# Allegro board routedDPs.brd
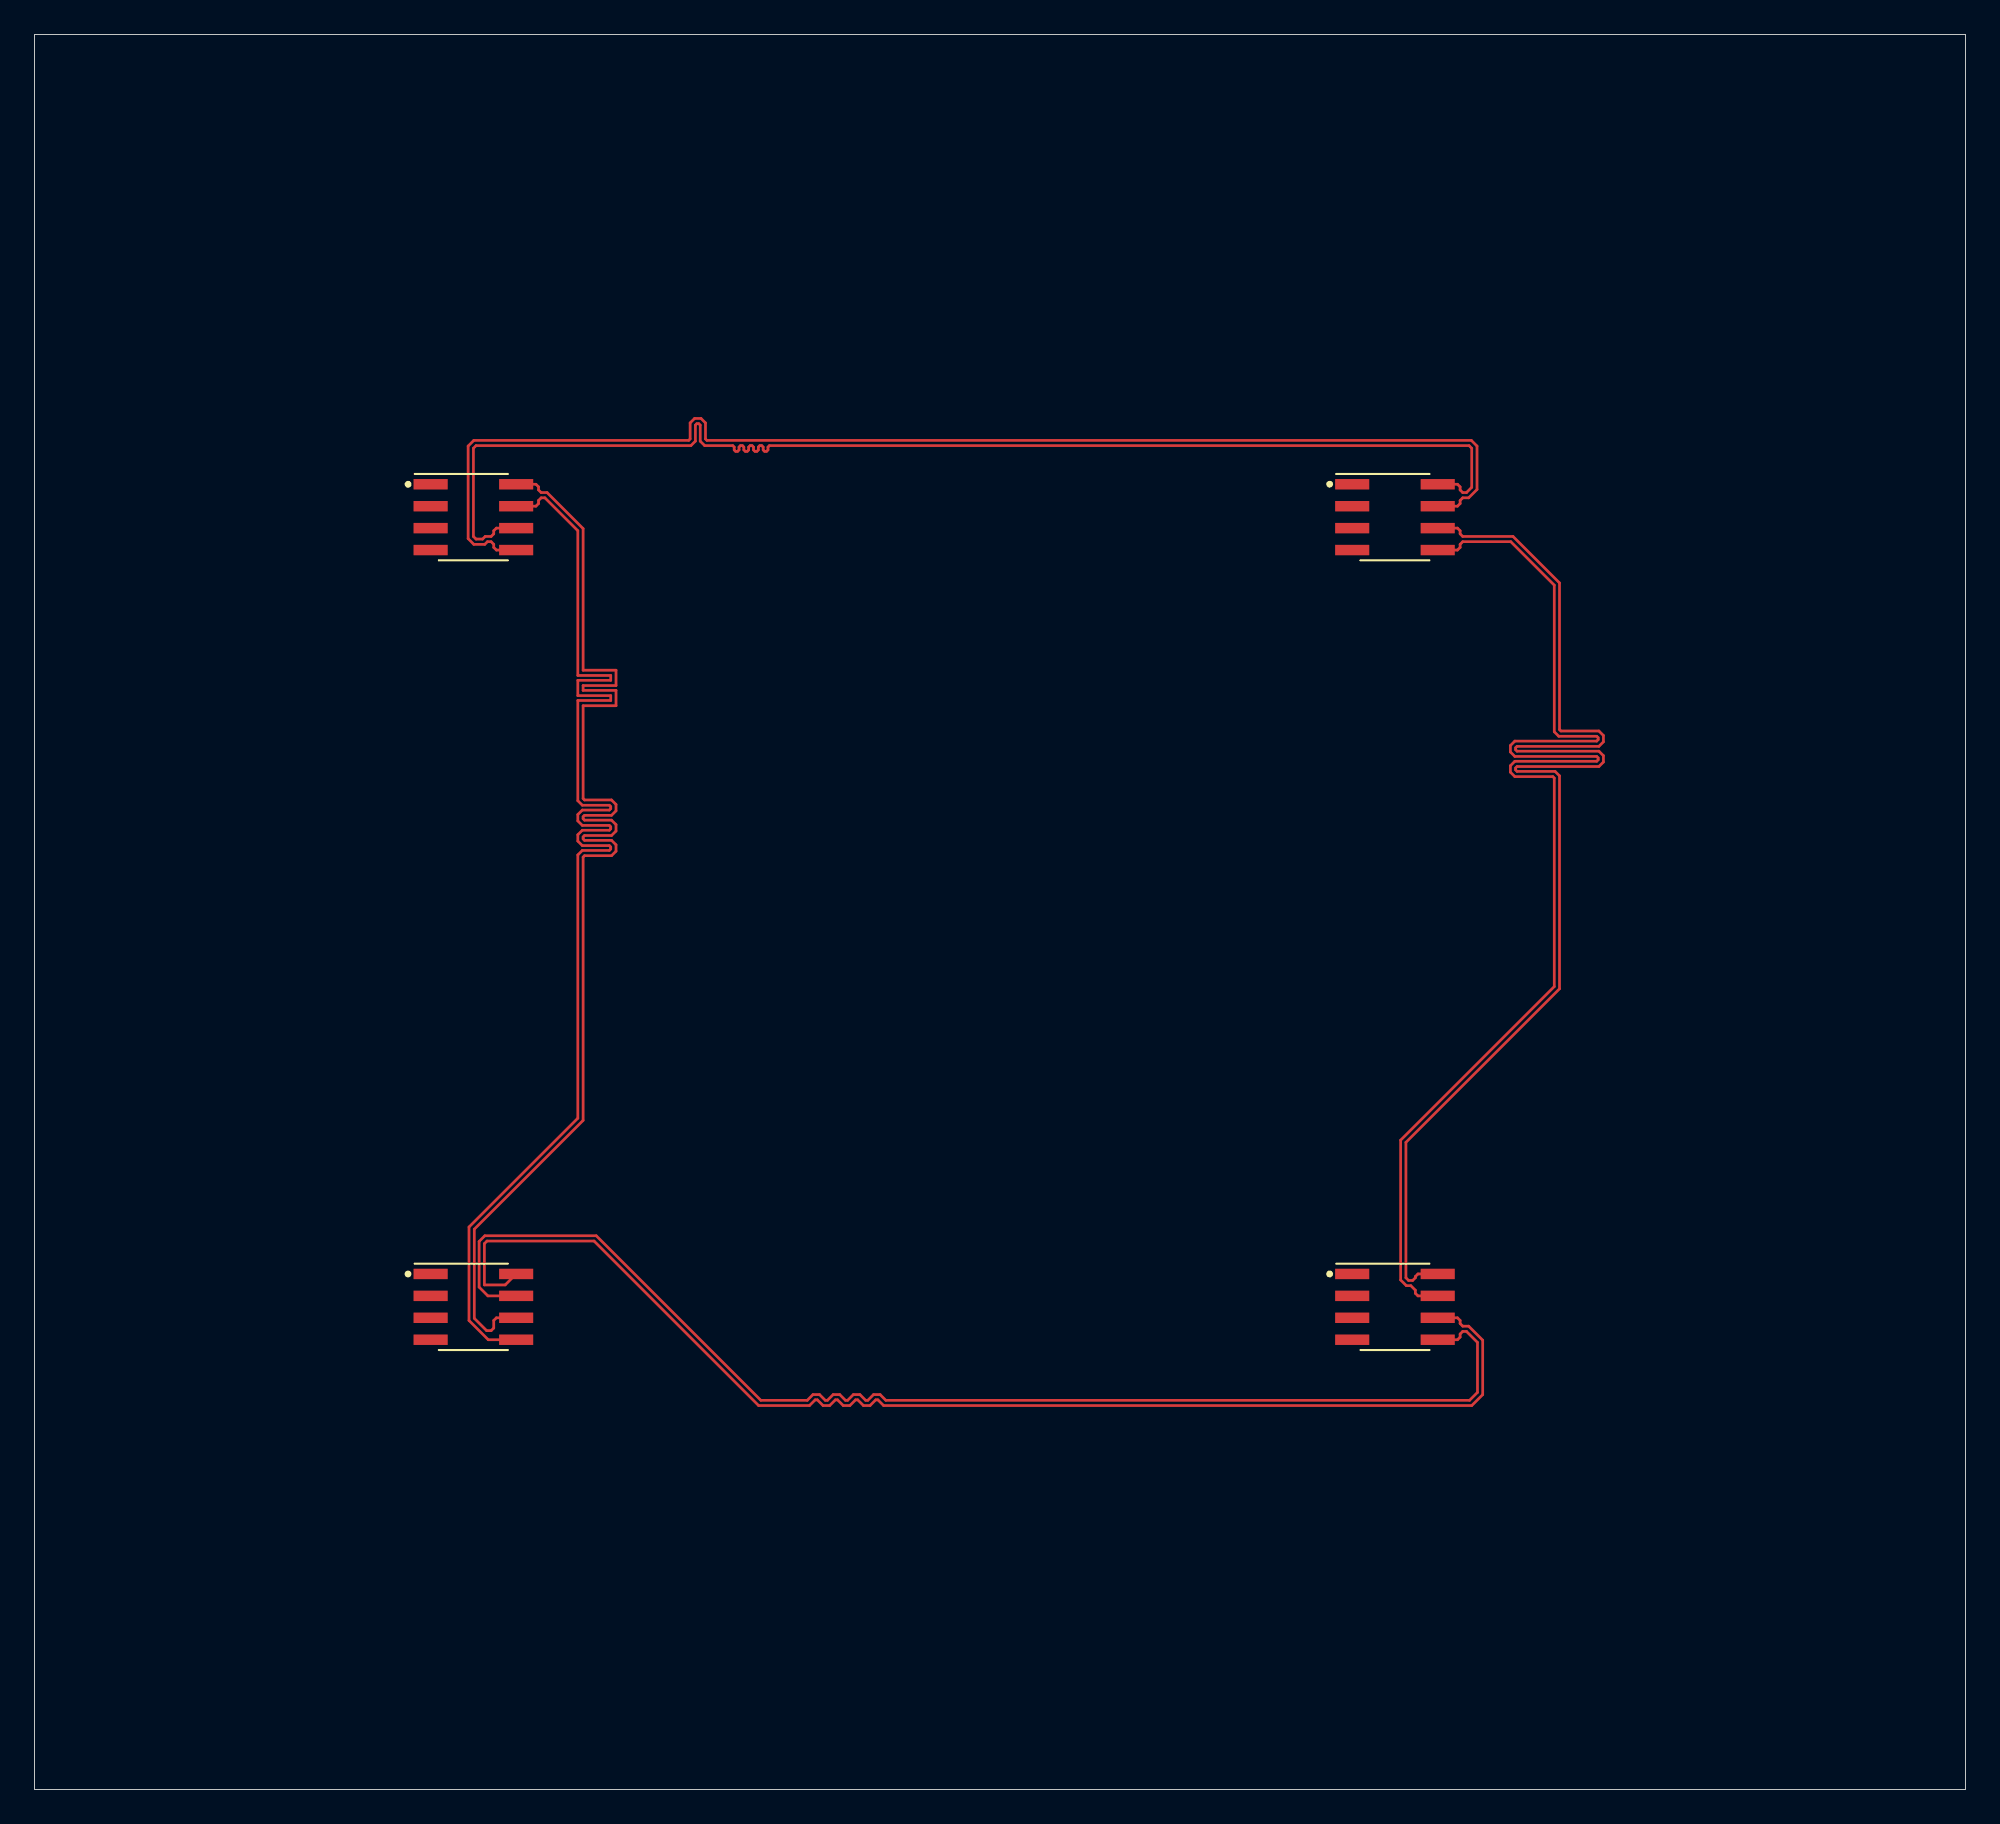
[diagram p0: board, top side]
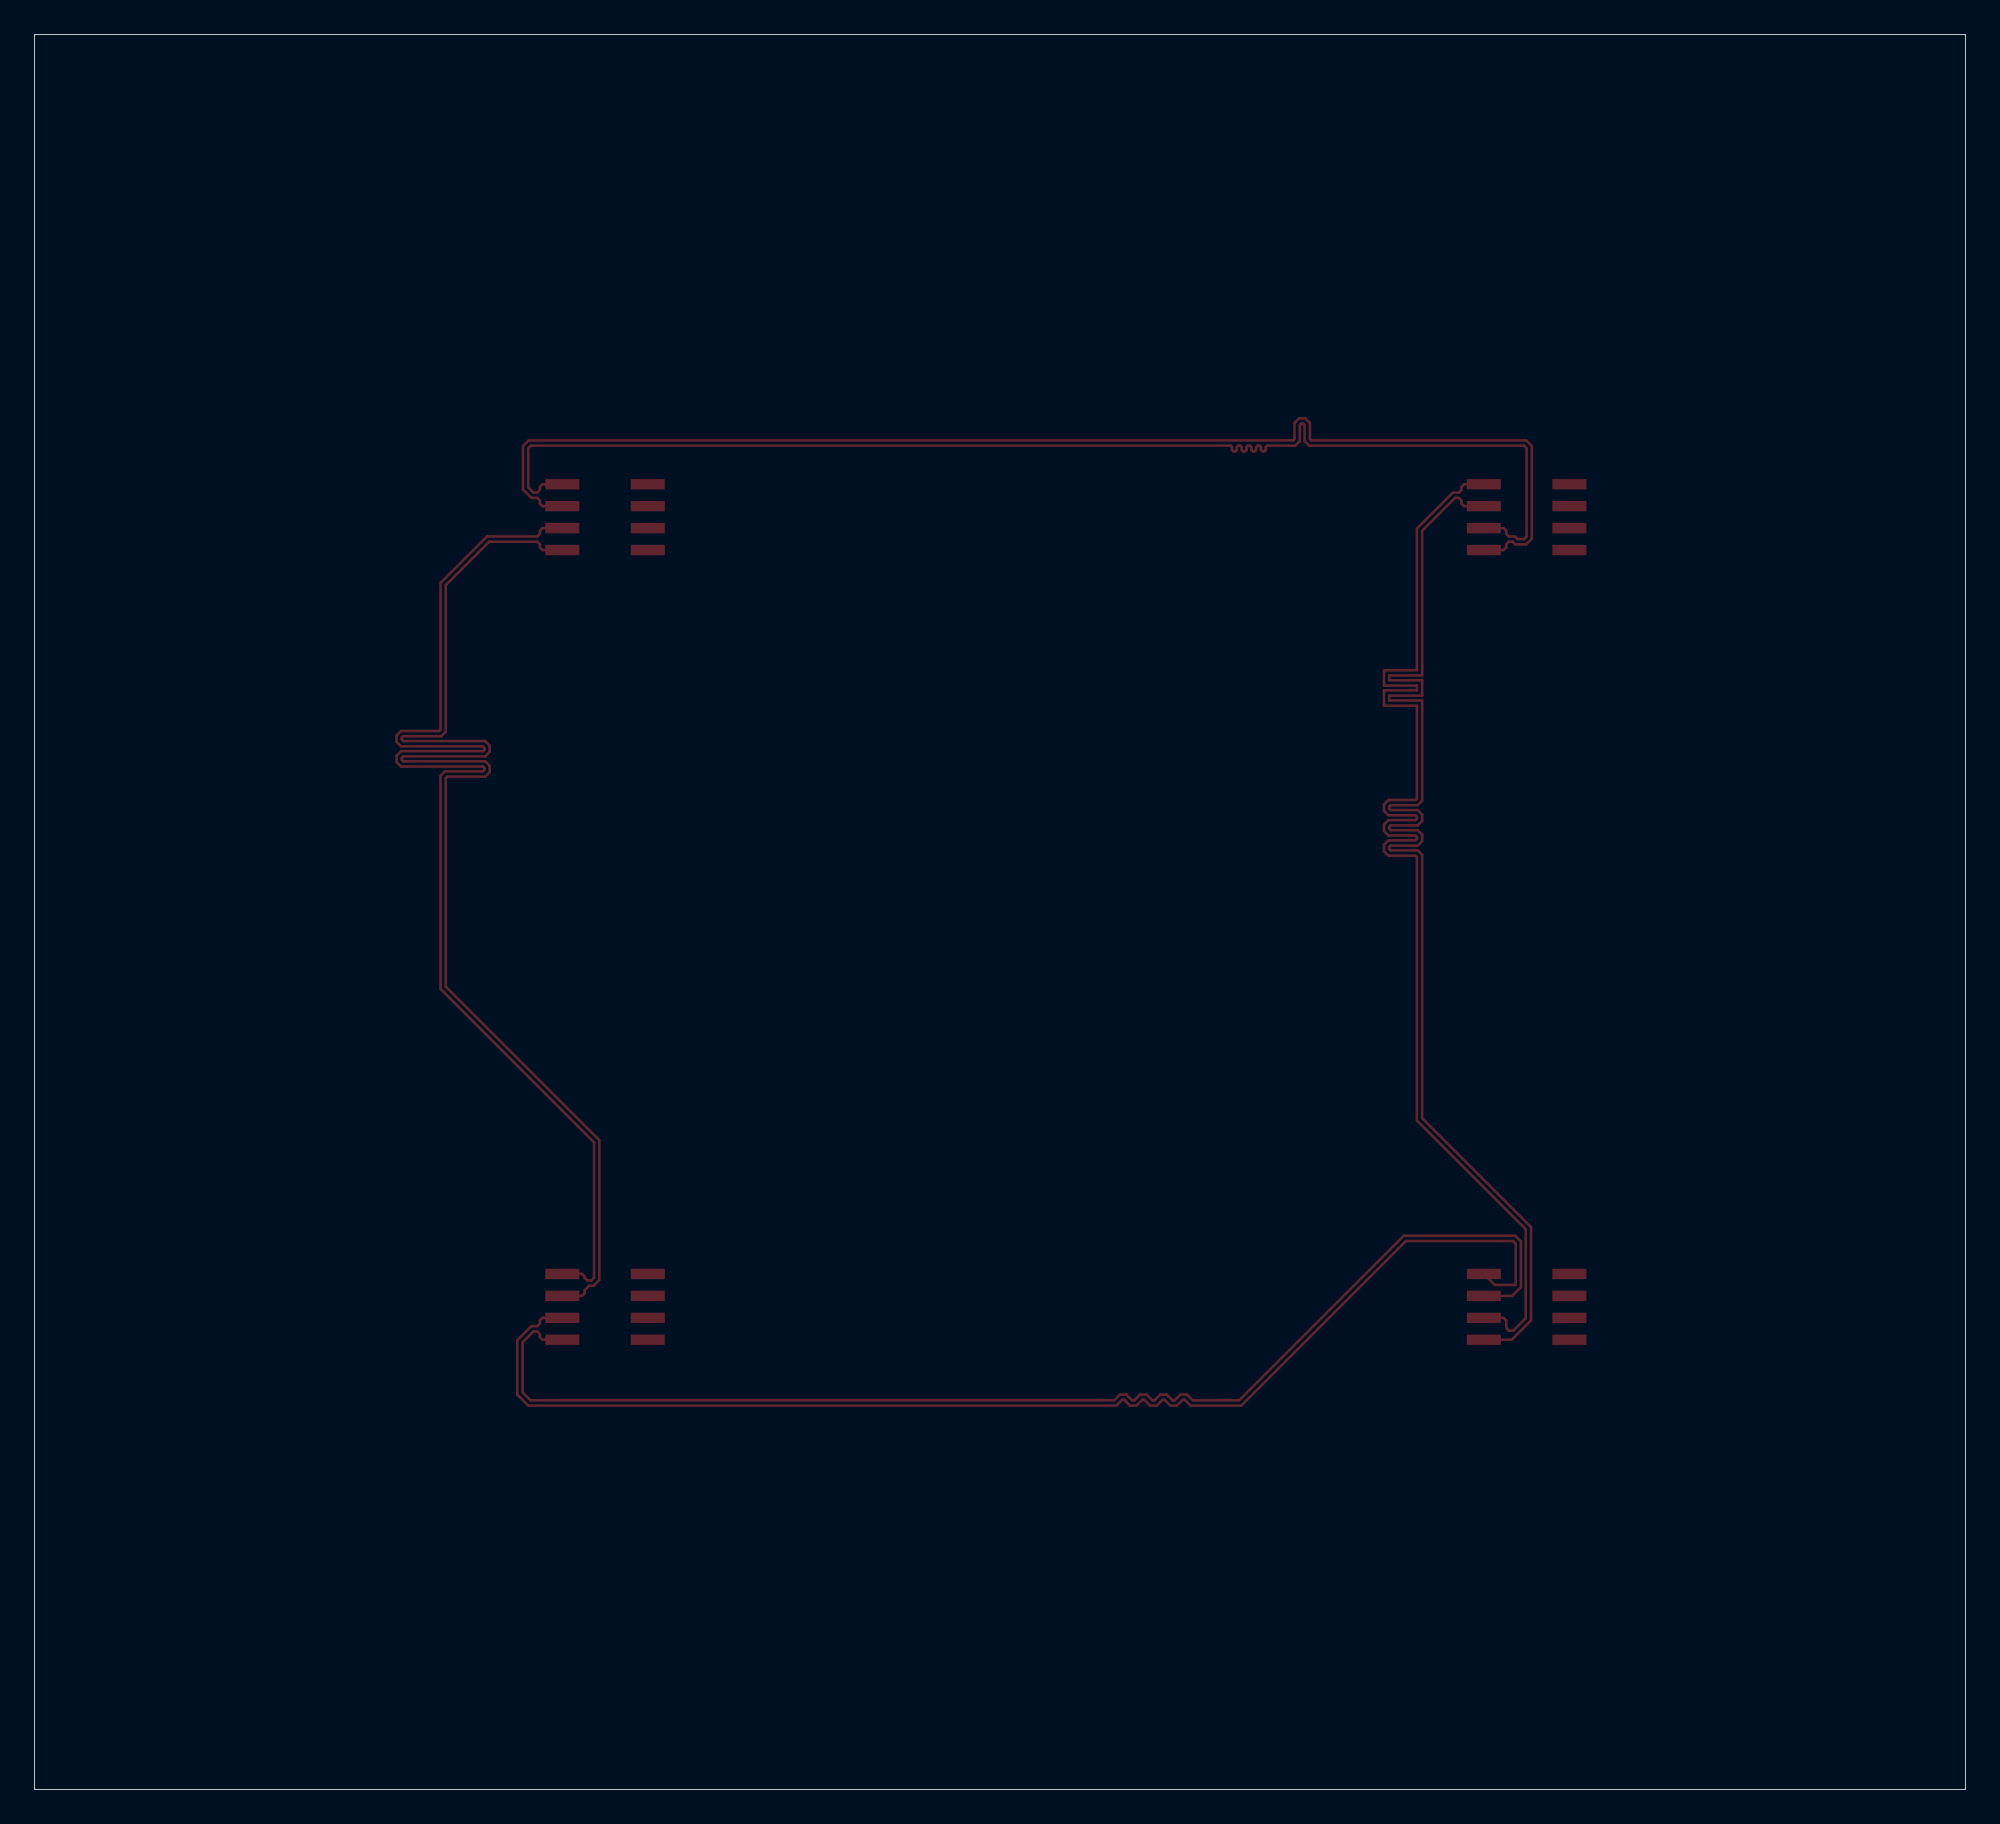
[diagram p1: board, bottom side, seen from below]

Outline 111.76 x 101.6 mm; copper layers: TOP, GND, VCC, BOTTOM. Coordinates in mm from the lower left corner of the outline.
Outline path: 0,101.6 0,0 111.76,0 111.76,101.6 0,101.6

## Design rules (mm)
net group D3: nets D3N D3P
net group D4: nets D4N D4P

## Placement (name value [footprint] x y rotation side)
U1  DS89C21  [SOIC127P600X175-8L87N]  25.4 73.66 270 top
U2  DS89C21  [SOIC127P600X175-8L87N]  78.74 73.66 270 top
U3  DS89C21  [SOIC127P600X175-8L87N]  78.74 27.94 270 top
U4  DS89C21  [SOIC127P600X175-8L87N]  25.4 27.94 270 top

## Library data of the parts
U1-U4 = DS89C21

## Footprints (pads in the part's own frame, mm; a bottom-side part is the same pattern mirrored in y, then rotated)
SOIC127P600X175-8L87N
  rect 0.6x1.97 smd: 1(-1.905,-2.475) 2(-0.635,-2.475) 3(0.635,-2.475) 4(1.905,-2.475) 5(1.905,2.475) 6(0.635,2.475) 7(-0.635,2.475) 8(-1.905,2.475)

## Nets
GND: U1.4(GND) U2.4(GND) U3.4(GND) U4.4(GND)
VCC: U1.1(VCC) U2.1(VCC) U3.1(VCC) U4.1(VCC)
D1N: U1.5(D_N) U2.7(R_N)
D1P: U1.6(D_P) U2.8(R_P)
D2N: U2.5(D_N) U3.7(R_N)
D2P: U2.6(D_P) U3.8(R_P)
D3N: U3.5(D_N) U4.7(R_N)
D3P: U3.6(D_P) U4.8(R_P)
D4N: U1.7(R_N) U4.5(D_N)
D4P: U1.8(R_P) U4.6(D_P)
X1: U1.2(RO) U2.3(DI)
X2: U2.2(RO) U3.3(DI)
X3: U3.2(RO) U4.3(DI)
X4: U1.3(DI) U4.2(RO)

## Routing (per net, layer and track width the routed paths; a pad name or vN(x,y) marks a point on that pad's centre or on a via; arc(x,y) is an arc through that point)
D1N: length 74.7
  TOP w0.152: U2.7 82.36,74.3 82.51,74.45 82.51,74.63 82.66,74.78 83.01,74.78 83.49,75.26 83.49,77.77 83.16,78.11 38.92,78.11 38.83,78.19 38.83,79.11 38.57,79.38 38.2,79.38 37.94,79.11 37.94,78.19 37.86,78.11 25.43,78.11 25.1,77.77 25.1,72.42 25.43,72.09 26.06,72.09 26.21,72.24 26.43,72.24 26.58,72.09 26.58,71.91 26.73,71.75 U1.5
D1P: length 74.6
  TOP w0.152: U1.6 26.73,73.02 26.58,72.87 26.58,72.69 26.43,72.54 26.08,72.54 25.93,72.39 25.55,72.39 25.4,72.54 25.4,77.65 25.55,77.8 37.99,77.8 38.25,78.06 38.25,78.99 38.33,79.07 38.45,79.07 38.53,78.99 38.53,78.06 38.79,77.8 40.41,77.8 40.5,77.72 40.5,77.55 40.58,77.47 40.69,77.47 40.77,77.55 40.77,77.72 40.86,77.8 40.97,77.8 41.05,77.72 41.05,77.55 41.14,77.47 41.25,77.47 41.33,77.55 41.33,77.72 41.42,77.8 41.53,77.8 41.61,77.72 41.61,77.55 41.69,77.47 41.81,77.47 41.89,77.55 41.89,77.72 41.97,77.8 42.09,77.8 42.17,77.72 42.17,77.55 42.25,77.47 42.37,77.47 42.45,77.55 42.45,77.72 42.53,77.8 83.03,77.8 83.19,77.65 83.19,75.39 82.88,75.08 82.66,75.08 82.51,75.23 82.51,75.41 82.36,75.56 U2.8
D2N: length 73.9
  TOP w0.152: U3.7 80.07,28.58 79.92,28.73 79.92,28.91 79.66,29.17 79.4,29.17 79.07,29.5 79.07,37.59 87.96,46.48 87.96,58.56 87.88,58.64 85.68,58.64 85.42,58.9 85.42,59.27 85.68,59.53 90.42,59.53 90.5,59.61 90.5,59.72 90.42,59.81 85.68,59.81 85.42,60.07 85.42,60.43 85.68,60.69 90.42,60.69 90.5,60.78 90.5,60.89 90.42,60.97 88.22,60.97 87.96,61.23 87.96,69.72 85.45,72.24 82.66,72.24 82.51,72.09 82.51,71.91 82.36,71.75 U2.5
D2P: length 73.8
  TOP w0.152: U2.6 82.36,73.02 82.51,72.87 82.51,72.69 82.66,72.54 85.57,72.54 88.27,69.85 88.27,61.36 88.35,61.28 90.54,61.28 90.8,61.02 90.8,60.65 90.54,60.39 85.81,60.39 85.72,60.31 85.72,60.19 85.81,60.11 90.54,60.11 90.8,59.85 90.8,59.48 90.54,59.22 85.81,59.22 85.72,59.14 85.72,59.02 85.81,58.94 88,58.94 88.27,58.68 88.27,46.35 79.38,37.46 79.38,29.62 79.53,29.47 79.77,29.47 79.92,29.62 79.92,29.69 80.07,29.84 U3.8
D3N: length 73.9
  TOP w0.152: U3.5 82.36,26.03 82.51,26.19 82.51,26.37 82.66,26.52 82.88,26.52 83.52,25.88 83.52,22.99 83.06,22.53 49.27,22.53 48.94,22.86 48.56,22.86 48.23,22.53 48.1,22.53 47.77,22.86 47.39,22.86 47.06,22.53 46.93,22.53 46.6,22.86 46.22,22.86 45.89,22.53 45.77,22.53 45.44,22.86 45.06,22.86 44.72,22.53 42.04,22.53 32.51,32.05 26.06,32.05 25.73,31.72 25.73,29.08 26.24,28.58 U4.7
D3P: length 74
  TOP w0.152: U4.8 27.24,29.21 26.03,29.21 26.03,31.6 26.19,31.75 32.38,31.75 41.91,22.23 44.85,22.23 45.18,22.56 45.31,22.56 45.64,22.23 46.02,22.23 46.35,22.56 46.48,22.56 46.81,22.23 47.19,22.23 47.52,22.56 47.65,22.56 47.98,22.23 48.36,22.23 48.69,22.56 48.81,22.56 49.14,22.23 83.19,22.23 83.82,22.86 83.82,26.01 83.01,26.82 82.66,26.82 82.51,26.97 82.51,27.15 82.36,27.3 U3.6
D4N: length 74
  TOP w0.152: U1.7 29.02,74.3 29.17,74.45 29.17,74.63 29.32,74.78 29.54,74.78 31.45,72.87 31.45,64.49 33.35,64.49 33.35,64.21 31.45,64.21 31.45,63.33 33.35,63.33 33.35,63.05 31.45,63.05 31.45,57.24 31.71,56.98 33.27,56.98 33.35,56.9 33.35,56.78 33.27,56.7 31.71,56.7 31.45,56.44 31.45,56.07 31.71,55.81 33.27,55.81 33.35,55.73 33.35,55.62 33.27,55.53 31.71,55.53 31.45,55.27 31.45,54.9 31.71,54.64 33.27,54.64 33.35,54.56 33.35,54.45 33.27,54.37 31.71,54.37 31.45,54.11 31.45,38.86 25.15,32.56 25.15,27.15 26.26,26.03 U4.5
D4P: length 74.5
  TOP w0.152: U4.6 26.73,27.3 26.58,27.15 26.58,26.71 26.43,26.56 26.17,26.56 25.45,27.28 25.45,32.44 31.75,38.73 31.75,53.98 31.83,54.06 33.39,54.06 33.66,54.32 33.66,54.69 33.39,54.95 31.83,54.95 31.75,55.03 31.75,55.15 31.83,55.23 33.39,55.23 33.66,55.49 33.66,55.86 33.39,56.12 31.83,56.12 31.75,56.2 31.75,56.32 31.83,56.4 33.39,56.4 33.66,56.66 33.66,57.03 33.39,57.29 31.83,57.29 31.75,57.37 31.75,62.74 33.66,62.74 33.66,63.63 31.75,63.63 31.75,63.91 33.66,63.91 33.66,64.8 31.75,64.8 31.75,73 29.67,75.08 29.32,75.08 29.17,75.23 29.17,75.41 29.02,75.56 U1.8

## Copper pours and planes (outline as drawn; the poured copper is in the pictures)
GND on GND: 0.51,101.09 111.25,101.09 111.25,0.51 0.51,0.51
Net_1 on VCC: 0.51,101.09 111.25,101.09 111.25,0.51 0.51,0.51
